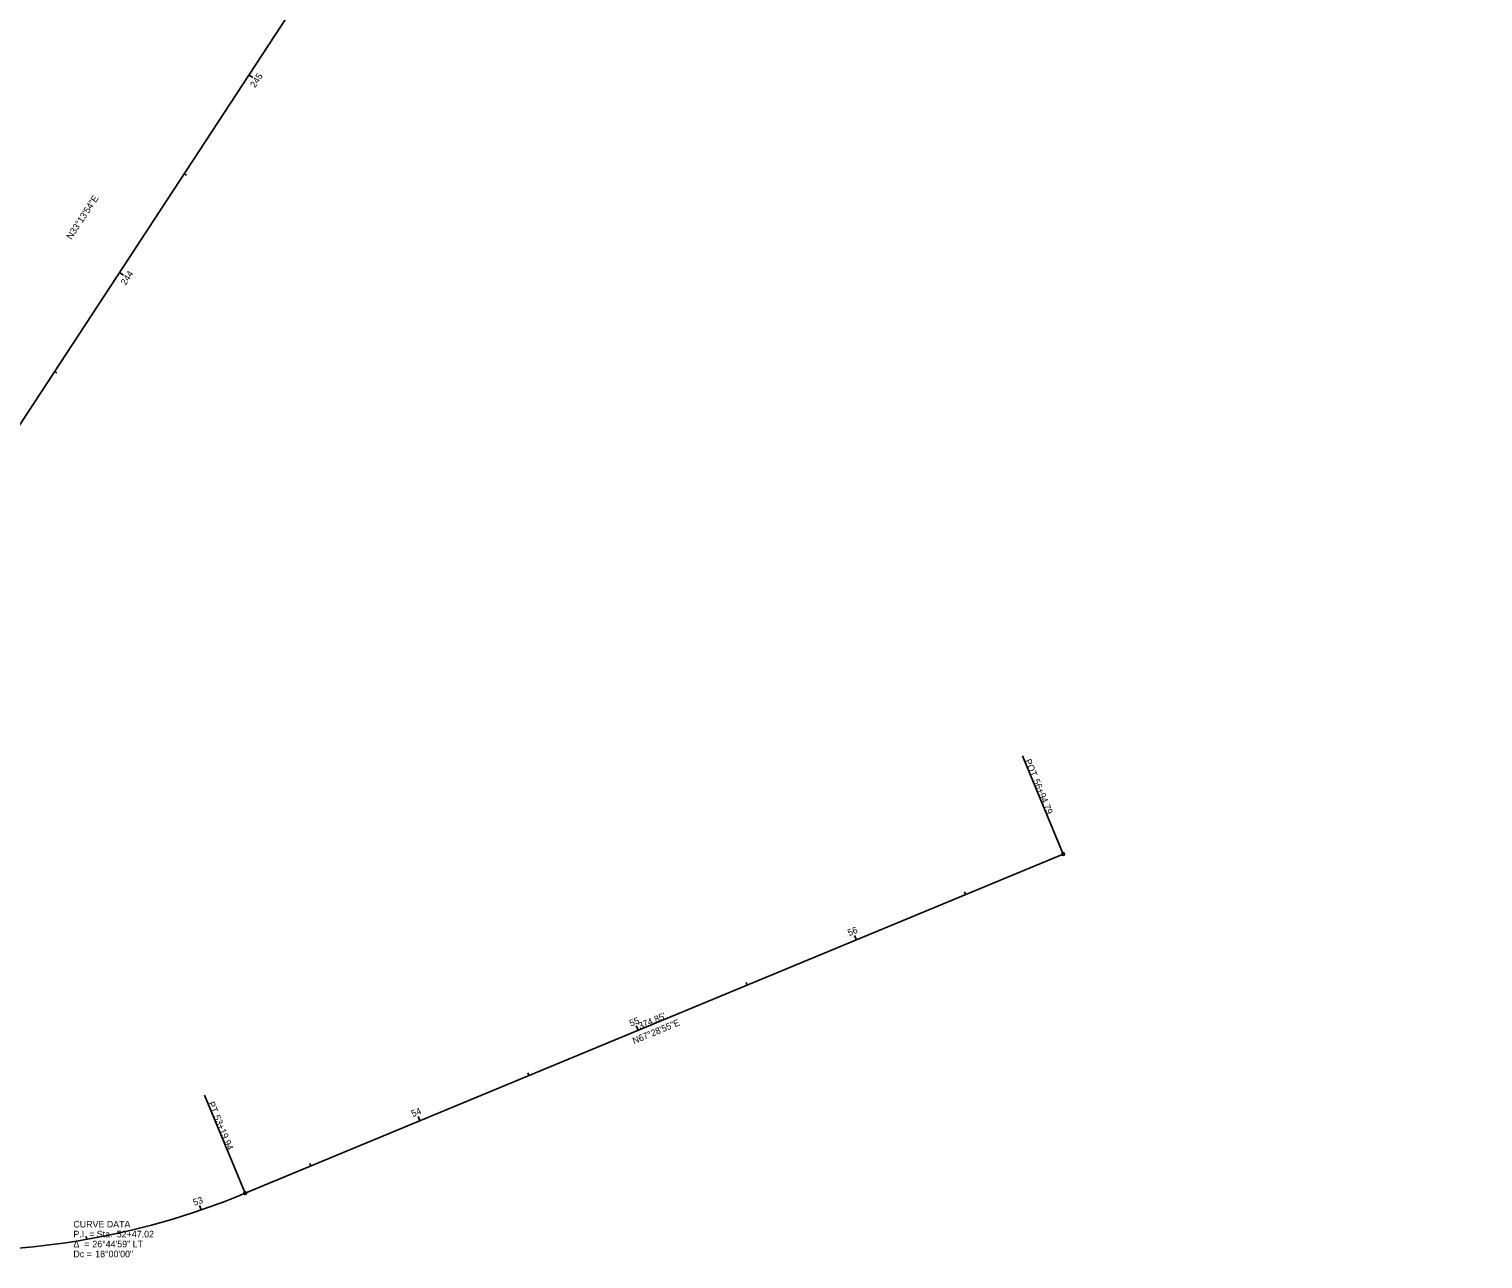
# Model space of a CAD drawing. Extents: x 1459328 to 1461822, y 481336 to 484746.
# Drawn here: x 1460553 to 1461169, y 482508 to 483028 of the extents above; entities that cross this region are included whole.
import ezdxf

# ---------------------------------------------------------------- set-up
doc = ezdxf.new("R2010")
doc.units = 0
for name, color, linetype in [('_CIVIL_CONSTRUCTION', 7, 'Continuous'), ('BR_X_SV_Abut', 7, 'Continuous'), ('DR_X_Ditch', 7, 'Continuous'), ('DR_X_Elev_Flow', 7, 'Continuous'), ('PM_X_Cells', 7, 'Continuous'), ('PM_X_Surveyed_Line', 7, 'Continuous'), ('PV_X_COP', 7, 'Continuous'), ('PV_X_Curb', 7, 'Continuous'), ('PV_X_EOP', 7, 'Continuous'), ('PV_X_Shoulder_Aggregate', 7, 'Continuous'), ('RD_X_GR_Bar', 7, 'Continuous'), ('RD_X_GR_Lt', 7, 'Continuous'), ('RD_X_GR_Rt', 7, 'Continuous'), ('RW_X_Esmt_SH', 7, 'Continuous'), ('SN_X_Public', 7, 'Continuous'), ('SV_X_Break_Lines', 7, 'Continuous'), ('SV_X_Mon_Cells_Found', 7, 'Continuous'), ('SV_X_Random_Point', 7, 'Continuous'), ('SV_X_Toe_of_Slope', 7, 'Continuous'), ('SV_X_Top_of_Bank', 7, 'Continuous'), ('UT_X_Electric_Cells', 7, 'Continuous'), ('UT_X_Sanitary_Cells', 7, 'Continuous'), ('VG_X_Cells', 7, 'Continuous')]:
    doc.layers.add(name, color=color, linetype=linetype)

msp = doc.modelspace()

# ---------------------------------------------------------------- linework, layer by layer
at = {"layer": '_CIVIL_CONSTRUCTION'}
msp.add_line((1459566.19, 481360.47), (1461783.98, 484745.51), dxfattribs=at)
at = {"layer": 'BR_X_SV_Abut'}
for p, q in [((1460990.95, 482679.25), (1460973.71, 482720.82)), ((1460644.68, 482535.69), (1460627.44, 482577.26))]:
    msp.add_line(p, q, dxfattribs=at)
for centre in [(1460990.95, 482679.25), (1460644.68, 482535.69)]:
    msp.add_circle(centre, 0.6, dxfattribs=at)
at = {"layer": 'DR_X_Ditch'}
msp.add_line((1460646.25, 483008.98), (1460647.25, 483008.32), dxfattribs=at)
at = {"layer": 'PV_X_EOP'}
for p, q in [((1460949.57, 482662.09), (1460949.11, 482663.2)), ((1460903.38, 482642.94), (1460902.62, 482644.79)), ((1460857.2, 482623.8), (1460856.74, 482624.9)), ((1460811.01, 482604.65), (1460810.24, 482606.49)), ((1460764.82, 482585.5), (1460764.36, 482586.61)), ((1460718.63, 482566.35), (1460717.87, 482568.2)), ((1460672.45, 482547.2), (1460671.99, 482548.31)), ((1460626.03, 482528.63), (1460625.38, 482530.53)), ((1460577.66, 482516.19), (1460577.45, 482517.37))]:
    msp.add_line(p, q, dxfattribs=at)
at = {"layer": 'PV_X_Shoulder_Aggregate'}
for p, q in [((1460990.95, 482679.25), (1460973.71, 482720.82)), ((1460644.68, 482535.69), (1460627.44, 482577.26))]:
    msp.add_line(p, q, dxfattribs=at)
for centre in [(1460990.95, 482679.25), (1460644.68, 482535.69)]:
    msp.add_circle(centre, 0.6, dxfattribs=at)
at = {"layer": 'RD_X_GR_Lt'}
msp.add_line((1460811.01, 482604.65), (1460810.55, 482605.76), dxfattribs=at)
at = {"layer": 'RW_X_Esmt_SH'}
msp.add_line((1460644.68, 482535.69), (1460990.95, 482679.25), dxfattribs=at)
msp.add_line((1460644.68, 482535.69), (1460990.95, 482679.25), dxfattribs=at)
msp.add_arc((1460522.77, 482829.73), 318.31, 265.76832, 292.51811, dxfattribs=at)
msp.add_arc((1460522.77, 482829.73), 318.31, 265.76832, 292.51811, dxfattribs=at)
at = {"layer": 'SV_X_Break_Lines'}
for p, q in [((1460903.38, 482642.94), (1460902.93, 482644.05)), ((1460811.01, 482604.65), (1460810.24, 482606.49)), ((1460718.63, 482566.35), (1460718.17, 482567.46)), ((1460626.03, 482528.63), (1460625.64, 482529.77))]:
    msp.add_line(p, q, dxfattribs=at)
at = {"layer": 'SV_X_Top_of_Bank'}
for p, q in [((1460990.95, 482679.25), (1460973.71, 482720.82)), ((1460644.68, 482535.69), (1460627.44, 482577.26))]:
    msp.add_line(p, q, dxfattribs=at)
for centre in [(1460990.95, 482679.25), (1460644.68, 482535.69)]:
    msp.add_circle(centre, 0.6, dxfattribs=at)
at = {"layer": 'UT_X_Electric_Cells'}
for p, q in [((1460646.25, 483008.98), (1460647.92, 483007.88)), ((1460618.84, 482967.15), (1460619.85, 482966.5)), ((1460591.44, 482925.33), (1460593.12, 482924.24)), ((1460564.04, 482883.51), (1460565.04, 482882.85))]:
    msp.add_line(p, q, dxfattribs=at)
at = {"layer": 'UT_X_Sanitary_Cells'}
for p, q in [((1460646.25, 483008.98), (1460647.92, 483007.88)), ((1460591.44, 482925.33), (1460592.45, 482924.67))]:
    msp.add_line(p, q, dxfattribs=at)

# ---------------------------------------------------------------- texts
at = {"layer": 'BR_X_SV_Abut'}
for s, p in [('POT', (1460974.61, 482718.77)), ('56+94.79', (1460978.11, 482710.33)), ('PT', (1460628.93, 482573.79)), ('53+19.94', (1460631.26, 482568.17))]:
    msp.add_text(s, height=2.8, rotation=292.51811, dxfattribs=at).set_placement(p)
at = {"layer": 'DR_X_Elev_Flow'}
msp.add_text('N33°13\'54"E', height=2.8, rotation=56.76822, dxfattribs=at).set_placement((1460571.13, 482939.09))
at = {"layer": 'PM_X_Cells'}
msp.add_text("374.85'", height=2.8, rotation=22.51811, dxfattribs=at).set_placement((1460811.8, 482605.03))
at = {"layer": 'PM_X_Surveyed_Line'}
for s, p in [('CURVE DATA', (1460571.98, 482521.19)), ('P.I. = Sta. ', (1460571.98, 482516.99)), ('52+47.02', (1460590.35, 482516.99)), ('Δ  = ', (1460571.98, 482512.79)), ('26°44\'59" LT', (1460580, 482512.79)), ('Dc = ', (1460571.98, 482508.59)), ('18°00\'00"', (1460581.22, 482508.59))]:
    msp.add_text(s, height=2.8, dxfattribs=at).set_placement(p)
at = {"layer": 'PV_X_COP'}
msp.add_text('N67°28\'55"E', height=2.8, rotation=22.51811, dxfattribs=at).set_placement((1460809.32, 482598.75))
at = {"layer": 'PV_X_Curb'}
for s, p in [('CURVE DATA', (1460571.98, 482521.19)), ('P.I. = Sta. ', (1460571.98, 482516.99)), ('52+47.02', (1460590.35, 482516.99)), ('Δ  = ', (1460571.98, 482512.79)), ('26°44\'59" LT', (1460580, 482512.79)), ('Dc = ', (1460571.98, 482508.59)), ('18°00\'00"', (1460581.22, 482508.59))]:
    msp.add_text(s, height=2.8, dxfattribs=at).set_placement(p)
at = {"layer": 'PV_X_EOP'}
for s, rotation, p in [('56', 22.51811, (1460900.38, 482644.46)), ('55', 22.51811, (1460808, 482606.15)), ('54', 22.51811, (1460715.67, 482567.88)), ('53', 18.9286, (1460623.15, 482530.34))]:
    msp.add_text(s, height=2.8, rotation=rotation, dxfattribs=at).set_placement(p)
at = {"layer": 'PV_X_Shoulder_Aggregate'}
for s, p in [('POT', (1460974.61, 482718.77)), ('56+94.79', (1460978.11, 482710.33)), ('PT', (1460628.93, 482573.79)), ('53+19.94', (1460631.26, 482568.17))]:
    msp.add_text(s, height=2.8, rotation=292.51811, dxfattribs=at).set_placement(p)
at = {"layer": 'RD_X_GR_Bar'}
for s, p in [('CURVE DATA', (1460571.98, 482521.19)), ('P.I. = Sta. ', (1460571.98, 482516.99)), ('52+47.02', (1460590.35, 482516.99)), ('Δ  = ', (1460571.98, 482512.79)), ('26°44\'59" LT', (1460580, 482512.79)), ('Dc = ', (1460571.98, 482508.59)), ('18°00\'00"', (1460581.22, 482508.59))]:
    msp.add_text(s, height=2.8, dxfattribs=at).set_placement(p)
at = {"layer": 'RD_X_GR_Rt'}
msp.add_text('N67°28\'55"E', height=2.8, rotation=22.51811, dxfattribs=at).set_placement((1460809.32, 482598.75))
at = {"layer": 'SN_X_Public'}
msp.add_text("374.85'", height=2.8, rotation=22.51811, dxfattribs=at).set_placement((1460811.8, 482605.03))
at = {"layer": 'SV_X_Break_Lines'}
msp.add_text('55', height=2.8, rotation=22.51811, dxfattribs=at).set_placement((1460808, 482606.15))
at = {"layer": 'SV_X_Mon_Cells_Found'}
msp.add_text('N33°13\'54"E', height=2.8, rotation=56.76822, dxfattribs=at).set_placement((1460571.13, 482939.09))
at = {"layer": 'SV_X_Random_Point'}
msp.add_text("374.85'", height=2.8, rotation=22.51811, dxfattribs=at).set_placement((1460811.8, 482605.03))
at = {"layer": 'SV_X_Toe_of_Slope'}
msp.add_text('N67°28\'55"E', height=2.8, rotation=22.51811, dxfattribs=at).set_placement((1460809.32, 482598.75))
at = {"layer": 'SV_X_Top_of_Bank'}
for s, p in [('POT', (1460974.61, 482718.77)), ('56+94.79', (1460978.11, 482710.33)), ('PT', (1460628.93, 482573.79)), ('53+19.94', (1460631.26, 482568.17))]:
    msp.add_text(s, height=2.8, rotation=292.51811, dxfattribs=at).set_placement(p)
at = {"layer": 'UT_X_Electric_Cells'}
for s, p in [('245', (1460648.87, 483003.32)), ('244', (1460594.1, 482919.72))]:
    msp.add_text(s, height=2.8, rotation=56.76822, dxfattribs=at).set_placement(p)
at = {"layer": 'UT_X_Sanitary_Cells'}
msp.add_text('245', height=2.8, rotation=56.76822, dxfattribs=at).set_placement((1460648.87, 483003.32))
at = {"layer": 'VG_X_Cells'}
msp.add_text('N33°13\'54"E', height=2.8, rotation=56.76822, dxfattribs=at).set_placement((1460571.13, 482939.09))

doc.saveas('drawing.dxf')
